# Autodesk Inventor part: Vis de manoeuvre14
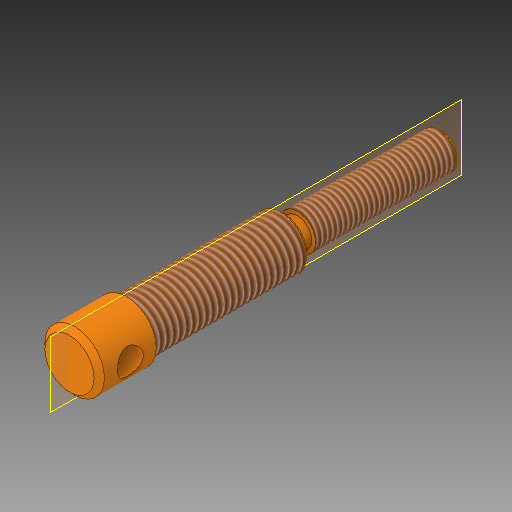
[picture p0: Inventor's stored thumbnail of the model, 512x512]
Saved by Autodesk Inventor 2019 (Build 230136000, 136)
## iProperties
Created: 2000-02
Part Number: Vis de manoeuvre14
Material: Générique
Document SubType Name: Modeling
Designer: si-nd67
Density: 1 g/cm^3
Appearance: Orange
Mass: 35.3877 g
Surface Area: 93.4305 cm^2
Volume: 35.3877 cm^3
Sending System: SolidWorks 2014
Last Author: tjost
Last Saved: 2019-02-07
Author: si-nd67
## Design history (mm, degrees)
feature "Enlèv. mat.-Extru.1"
feature "Filetage1" dims "d0" = 10, "d1" = 0
feature "Filetage2" dims "d2" = 10, "d3" = 0
node "Solide1"
